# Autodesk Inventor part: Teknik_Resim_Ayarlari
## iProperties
Company: Autodesk, Inc.
Shininess: 64.0
Length Units: 11269
Angle Units: 11279
Time Units: 11290
Mass Units: 11283
Length Display Precision: 3
Angle Display Precision: 2
Compacted: True
Part Number: Teknik_Resim_Ayarlari
Document SubType Name: Modeling
Created: 2003-11
Catalog Web Link: www.autodesk.com
Vendor: Autodesk, Inc.
Designer: Administrator
Manufacturer: Standard
Standards Organization: Custom
Density: 1 g/cm^3
Density: 0.0
Volumn: 0.0
Area: 0.0
PropertySet Name: Model Information
Control State: 0
Master: False
Checked Out: False
Author: Administrator
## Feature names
1. Extrusion1
2. Extrusion2
3. Extrusion4
